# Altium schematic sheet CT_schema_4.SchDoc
size 293 x 156 mm
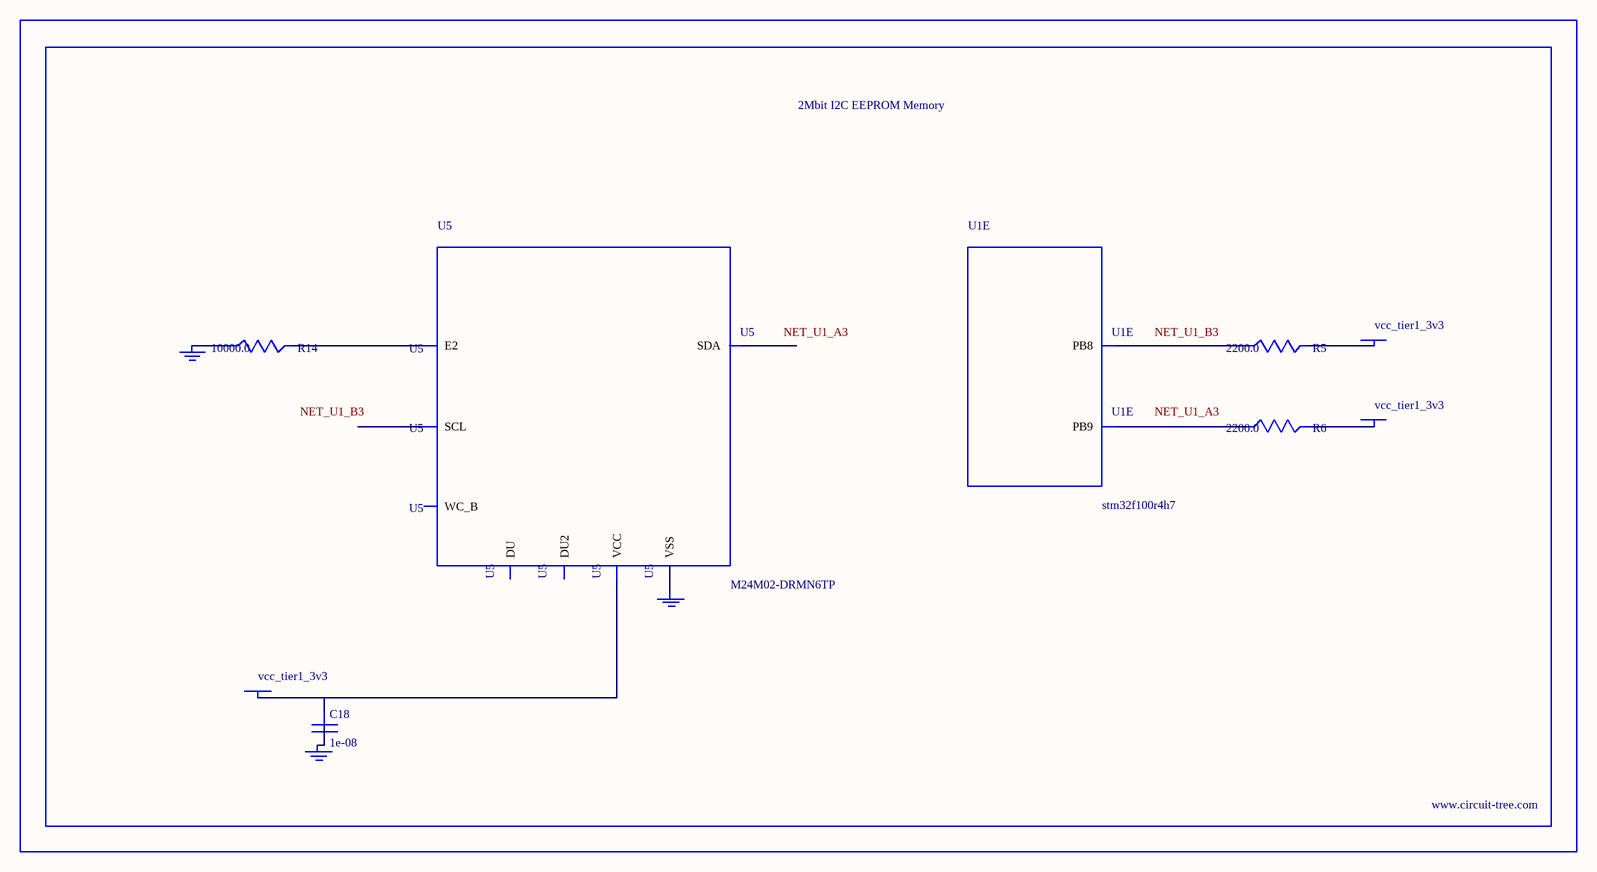
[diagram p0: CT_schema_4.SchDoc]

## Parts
BORDER3  (no value)
C18  1e-08  [C0402]
GND_INSTANCE_3_0  (no value)
GND_INSTANCE_3_1  (no value)
GND_INSTANCE_3_2  (no value)
POWER_INSTANCE_3_0  vcc_tier1_3v3
POWER_INSTANCE_3_1  vcc_tier1_3v3
POWER_INSTANCE_3_2  vcc_tier1_3v3
R5  2200.0  [R0603]
R6  2200.0  [R0603]
R14  10000.0  [R0603]
U1  stm32f100r4h7  [TFBGA64]  (part E of 5)
U5  M24M02-DRMN6TP  [SOIC-8]

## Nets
NetC18_1: C18.1 POWER_INSTANCE_3_0.0(PWR) U5.8(VCC)
NetC18_2: C18.2 GND_INSTANCE_3_1.0(GND)
NetGND_INSTANCE_3_0_0: GND_INSTANCE_3_0.0(GND) R14.1
NetGND_INSTANCE_3_2_0: GND_INSTANCE_3_2.0(GND) U5.4(VSS)
NetPOWER_INSTANCE_3_1_0: POWER_INSTANCE_3_1.0(PWR) R5.2
NetPOWER_INSTANCE_3_2_0: POWER_INSTANCE_3_2.0(PWR) R6.2
NetR5_1: R5.1 U1.B3(PB8)
NetR6_1: R6.1 U1.A3(PB9)
NetR14_2: R14.2 U5.3(E2)

Not connected (* = marked no-connect by the designer): U5 1(DU) 2(DU2) 5(SDA) 6(SCL) 7(WC_B)

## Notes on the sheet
- Labels drawn without touching a wire or pin: NET_U1_A3, NET_U1_B3

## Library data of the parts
BORDER3 = BORDER_PAGE3
C18 = C0402C103K3RAC
GND_INSTANCE_3_0-GND_INSTANCE_3_2 = GND
POWER_INSTANCE_3_0-POWER_INSTANCE_3_2 = PWR
R5 R6 = RC0603JR-072K2L
R14 = RC0603JR-0710KL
